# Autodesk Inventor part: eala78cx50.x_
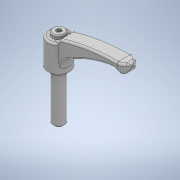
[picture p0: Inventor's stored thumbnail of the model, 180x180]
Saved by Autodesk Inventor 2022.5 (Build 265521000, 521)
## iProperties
Created: 2018-05
Part Number: eala78cx50.x_
Material: 一般
Document SubType Name: Modeling
Designer: imaocorp
Density: 1 g/cm^3
Appearance: 既定
Sending System: SOLIDWORKS 2016-2016286
MC: AMD64
MC_MODEL: AMD64 Family 21 Model 2 Stepping 0, AuthenticAMD
OS: Windows_NT
FRU: Parasolid Version 28.0, build 224,  7-29-2016
FORMAT: text
GUISE: transmit
KEY: eala78cx50
FILE: eala78cx50.x_t
DATE: Fri May 18 11:32:36 2018
Author: imaocorp
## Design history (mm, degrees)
feature "Base1"
node "ソリッド1"
